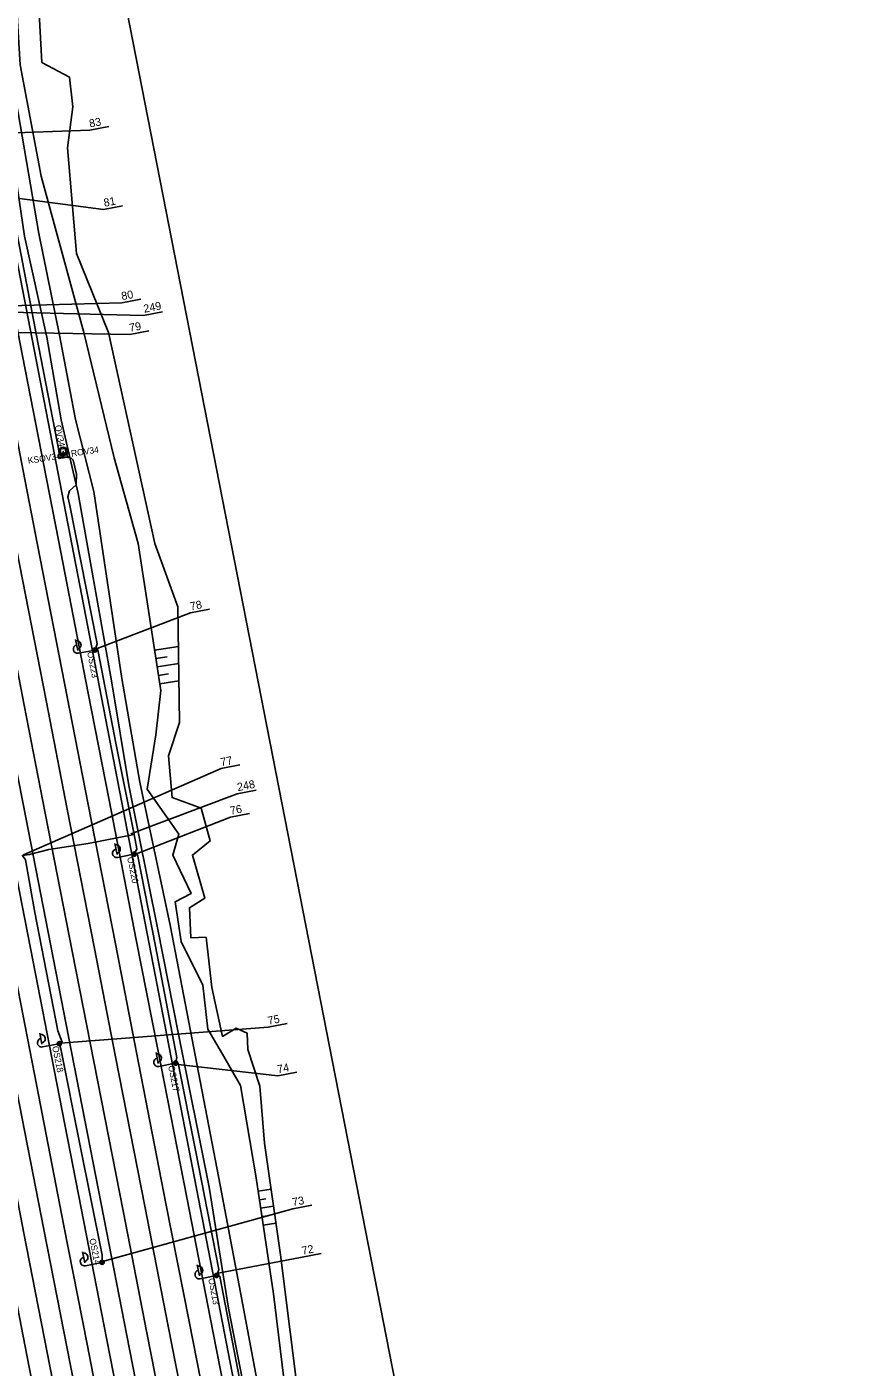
# Model space of a CAD drawing. Extents: x -545846 to -545044, y -1122650 to -1119108.
# Drawn here: x -545486.4 to -545292.2, y -1119892.9 to -1119578.9 of the extents above; entities that cross this region are included whole.
import ezdxf

# ---------------------------------------------------------------- set-up
doc = ezdxf.new("R2010")
doc.units = 0
for name, color, linetype in [('osvětlené plochy-hodnota-obrys', 7, 'Continuous'), ('so180602', 7, 'Continuous'), ('Vrstva 1', 7, 'Continuous'), ('Vrstva 10', 7, 'Continuous'), ('Vrstva 12', 7, 'Continuous'), ('Vrstva 12 - Trakce zaklady', 7, 'Continuous'), ('Vrstva 25', 7, 'Continuous'), ('Vrstva 26', 7, 'Continuous'), ('Vrstva 51', 7, 'Continuous'), ('Vrstva 62', 7, 'Continuous'), ('Vrstva 63', 7, 'Continuous')]:
    doc.layers.add(name, color=color, linetype=linetype)

msp = doc.modelspace()

# ---------------------------------------------------------------- linework, layer by layer
at = {"layer": 'osvětlené plochy-hodnota-obrys'}
msp.add_lwpolyline([(-545520.97, -1119506.47), (-545505.64, -1119546.72), (-545397.93, -1120102.85)], dxfattribs=at)
at = {"layer": 'Vrstva 1'}
for points in [[(-545506.26, -1119584.98), (-545505.64, -1119588.18), (-545501.7, -1119608.65), (-545497.83, -1119628.61), (-545492.89, -1119654.09), (-545487.27, -1119682.92), (-545483.88, -1119700.28)], [(-545501.4, -1119584.04), (-545500.78, -1119587.18), (-545496.82, -1119607.62), (-545492.98, -1119627.32), (-545488.03, -1119652.82), (-545482.44, -1119681.62), (-545479.01, -1119699.16)], [(-545504.04, -1119675.3), (-545496.76, -1119712.41), (-545491.63, -1119738.67), (-545486.65, -1119764.12), (-545480.23, -1119797.01), (-545475.32, -1119822.26), (-545468.39, -1119857.8), (-545462.99, -1119885.43), (-545456.77, -1119917.38), (-545451.56, -1119944.05), (-545446.59, -1119969.43), (-545441.08, -1119997.67), (-545435.96, -1120023.86), (-545430.59, -1120051.32), (-545426.85, -1120070.67)], [(-545512.75, -1119680.06), (-545506.04, -1119714.37), (-545500.99, -1119740.29), (-545495.97, -1119766.06), (-545489.56, -1119798.98), (-545484.63, -1119824.29), (-545477.72, -1119859.75), (-545472.31, -1119887.47), (-545466.08, -1119919.33), (-545460.87, -1119946.03), (-545455.91, -1119971.4), (-545450.38, -1119999.68), (-545445.29, -1120025.77), (-545439.89, -1120053.38), (-545436.18, -1120072.49)], [(-545508.3, -1119678.31), (-545501.41, -1119713.42), (-545496.34, -1119739.4), (-545491.32, -1119765.12), (-545484.91, -1119797.95), (-545479.98, -1119823.28), (-545473.04, -1119858.81), (-545467.63, -1119886.5), (-545461.42, -1119918.35), (-545456.18, -1119945.11), (-545451.23, -1119970.49), (-545445.73, -1119998.73), (-545440.63, -1120024.76), (-545435.23, -1120052.38), (-545431.51, -1120071.58)], [(-545526.85, -1119682.75), (-545520.07, -1119717.38), (-545515.03, -1119743.16), (-545509.97, -1119769.03), (-545503.62, -1119801.64), (-545498.65, -1119827.09), (-545491.8, -1119862.23), (-545486.29, -1119890.47), (-545480.04, -1119922.41), (-545474.85, -1119948.96), (-545469.96, -1119974), (-545464.39, -1120002.62), (-545459.33, -1120028.63), (-545453.88, -1120056.52), (-545450.25, -1120075.23)], [(-545522.17, -1119681.81), (-545515.38, -1119716.42), (-545510.35, -1119742.18), (-545505.33, -1119768), (-545498.9, -1119800.89), (-545493.99, -1119826.04), (-545487.08, -1119861.49), (-545481.61, -1119889.46), (-545475.38, -1119921.42), (-545470.2, -1119947.95), (-545465.28, -1119973.13), (-545459.72, -1120001.56), (-545454.6, -1120027.72), (-545449.19, -1120055.51), (-545445.53, -1120074.31)], [(-545517.39, -1119681.15), (-545510.7, -1119715.36), (-545505.65, -1119741.28), (-545500.67, -1119766.98), (-545494.24, -1119799.96), (-545489.36, -1119825.02), (-545482.41, -1119860.61), (-545476.97, -1119888.48), (-545470.74, -1119920.36), (-545465.53, -1119946.97), (-545460.61, -1119972.16), (-545455.05, -1120000.65), (-545449.96, -1120026.74), (-545444.56, -1120054.41), (-545440.88, -1120073.4)], [(-545479.01, -1119699.16), (-545472.02, -1119735), (-545467.16, -1119760.06), (-545460.78, -1119792.8), (-545455.81, -1119818.06), (-545448.88, -1119853.56), (-545443.47, -1119881.24), (-545437.18, -1119913.5), (-545431.96, -1119940.16), (-545427.07, -1119965.24), (-545421.65, -1119993.22), (-545416.45, -1120019.83), (-545411.17, -1120046.97), (-545407.29, -1120066.86)], [(-545488.74, -1119701.59), (-545481.88, -1119736.77), (-545476.93, -1119762.15), (-545470.57, -1119794.82), (-545465.63, -1119820.17), (-545458.72, -1119855.56), (-545453.29, -1119883.26), (-545447, -1119915.44), (-545441.82, -1119942.01), (-545436.87, -1119967.3), (-545431.4, -1119995.48), (-545426.21, -1120021.98), (-545420.91, -1120049.23), (-545417.12, -1120068.78)], [(-545483.88, -1119700.28), (-545476.97, -1119735.85), (-545472.05, -1119761.11), (-545465.67, -1119793.73), (-545460.72, -1119819.17), (-545453.82, -1119854.52), (-545448.39, -1119882.15), (-545442.08, -1119914.38), (-545436.89, -1119940.99), (-545431.97, -1119966.29), (-545426.49, -1119994.32), (-545421.32, -1120020.9), (-545416.02, -1120048.08), (-545412.17, -1120067.81)], [(-545493.36, -1119705.37), (-545486.99, -1119737.85), (-545482.07, -1119763.16), (-545475.68, -1119795.84), (-545470.7, -1119821.28), (-545463.79, -1119856.66), (-545458.35, -1119884.48), (-545452.09, -1119916.55), (-545446.9, -1119943.08), (-545441.96, -1119968.35), (-545436.44, -1119996.63), (-545431.34, -1120022.9), (-545425.98, -1120050.33), (-545422.21, -1120069.77)]]:
    msp.add_lwpolyline(points, dxfattribs=at)
at = {"layer": 'Vrstva 10'}
msp.add_line((-545554.37, -1119108.31), (-545292.19, -1120447.89), dxfattribs=at)
at = {"layer": 'Vrstva 12'}
msp.add_lwpolyline([(-545478.58, -1119677.89), (-545478.41, -1119679.07), (-545477.17, -1119678.94), (-545477.4, -1119677.71), (-545478.58, -1119677.89)], dxfattribs=at)
at = {"layer": 'Vrstva 12 - Trakce zaklady'}
msp.add_lwpolyline([(-545478.58, -1119677.89), (-545478.41, -1119679.07), (-545477.17, -1119678.94), (-545477.4, -1119677.71), (-545478.58, -1119677.89)], dxfattribs=at)
at = {"layer": 'Vrstva 25'}
for p, q in [((-545474.47, -1119724.99), (-545474.98, -1119722.44)), ((-545470.9, -1119725), (-545474.34, -1119725.68)), ((-545470.18, -1119725.35), (-545470.91, -1119724.86)), ((-545469.94, -1119725.05), (-545470.73, -1119724.52)), ((-545465.27, -1119772.8), (-545465.78, -1119770.26)), ((-545461.7, -1119772.8), (-545465.13, -1119773.49)), ((-545460.97, -1119773.14), (-545461.7, -1119772.66)), ((-545460.73, -1119772.85), (-545461.53, -1119772.32)), ((-545482.85, -1119817.21), (-545483.36, -1119814.66)), ((-545479.28, -1119817.21), (-545482.72, -1119817.89)), ((-545478.56, -1119817.56), (-545479.29, -1119817.07)), ((-545478.32, -1119817.27), (-545479.11, -1119816.73)), ((-545455.63, -1119821.75), (-545456.14, -1119819.2)), ((-545452.06, -1119821.75), (-545455.5, -1119822.44)), ((-545451.34, -1119822.09), (-545452.07, -1119821.61)), ((-545451.1, -1119821.8), (-545451.89, -1119821.27)), ((-545472.83, -1119868.43), (-545473.34, -1119865.89)), ((-545469.26, -1119868.43), (-545472.7, -1119869.12)), ((-545468.54, -1119868.77), (-545469.27, -1119868.29)), ((-545468.3, -1119868.48), (-545469.09, -1119867.95)), ((-545445.98, -1119871.48), (-545446.48, -1119868.93)), ((-545442.41, -1119871.5), (-545445.84, -1119872.17)), ((-545441.68, -1119871.84), (-545442.41, -1119871.35)), ((-545441.44, -1119871.55), (-545442.24, -1119871.02))]:
    msp.add_line(p, q, dxfattribs=at)
for points in [[(-545477.03, -1119678.78), (-545476.89, -1119679.77), (-545478.87, -1119680.06), (-545479.01, -1119679.07), (-545477.03, -1119678.78)], [(-545476.55, -1119678.57), (-545476.41, -1119679.56), (-545478.39, -1119679.85), (-545478.53, -1119678.86), (-545476.55, -1119678.57)]]:
    msp.add_lwpolyline(points, dxfattribs=at)
for centre, radius in [((-545477.87, -1119678.39), 1), ((-545470.41, -1119724.91), 0.5), ((-545470.41, -1119724.91), 0.5), ((-545461.21, -1119772.7), 0.5), ((-545461.21, -1119772.7), 0.5), ((-545478.79, -1119817.12), 0.5), ((-545478.79, -1119817.12), 0.5), ((-545451.57, -1119821.65), 0.5), ((-545451.57, -1119821.65), 0.5), ((-545468.77, -1119868.33), 0.5), ((-545468.77, -1119868.33), 0.5), ((-545441.92, -1119871.4), 0.5), ((-545441.92, -1119871.4), 0.5)]:
    msp.add_circle(centre, radius, dxfattribs=at)
for centre, start, end in [((-545474.53, -1119724.7), 101.1718, 281.1718), ((-545474.71, -1119723.72), 280.4692, 101.8744), ((-545465.33, -1119772.51), 101.3492, 281.3492), ((-545465.51, -1119771.53), 280.6467, 102.0518), ((-545483.09, -1119815.93), 280.5247, 101.9298), ((-545482.91, -1119816.91), 101.2273, 281.2273), ((-545455.69, -1119821.46), 101.3274, 281.3274), ((-545455.88, -1119820.48), 280.6249, 102.03), ((-545472.89, -1119868.14), 101.3328, 281.3328), ((-545473.08, -1119867.16), 280.6302, 102.0353), ((-545446.04, -1119871.18), 101.0333, 281.0333), ((-545446.21, -1119870.2), 280.3307, 101.7359)]:
    msp.add_arc(centre, 1, start, end, dxfattribs=at)
at = {"layer": 'Vrstva 26'}
for points in [[(-545490.42, -1119618.51), (-545484.14, -1119651.23), (-545478.73, -1119678.93), (-545477.77, -1119679.65)], [(-545477.87, -1119678.39), (-545477.87, -1119678.39), (-545477.86, -1119678.62), (-545477.77, -1119679.01), (-545477.47, -1119679.21), (-545477.95, -1119679.42), (-545477.77, -1119679.65)], [(-545477.77, -1119679.65), (-545475.99, -1119679.96), (-545475.55, -1119680.44), (-545474.78, -1119683.72), (-545474.82, -1119686.21), (-545476.39, -1119687.61), (-545476.83, -1119689.04), (-545476.34, -1119691.05), (-545469.94, -1119723.46), (-545470.41, -1119724.91), (-545469.75, -1119724.85), (-545465.52, -1119747.09), (-545461.3, -1119768.11), (-545460.63, -1119771.47), (-545461.21, -1119772.7), (-545460.51, -1119772.81), (-545456.27, -1119794.26), (-545451.25, -1119820.33), (-545451.57, -1119821.65), (-545450.97, -1119821.66), (-545446.81, -1119842.43), (-545441.43, -1119870.01), (-545441.92, -1119871.4), (-545441.17, -1119871.61), (-545436.23, -1119897.54)], [(-545468.77, -1119868.33), (-545468.76, -1119866.68), (-545473.98, -1119840.62), (-545478.41, -1119818.36), (-545478.79, -1119817.12), (-545478.11, -1119816.77), (-545479.15, -1119814.09), (-545484.55, -1119786.38), (-545486.75, -1119774.08), (-545487.42, -1119773.02), (-545485.8, -1119772.82), (-545481.22, -1119771.65), (-545472.05, -1119770.2), (-545461.3, -1119768.11)], [(-545485.8, -1119772.82), (-545481.22, -1119771.65), (-545472.05, -1119770.2), (-545461.3, -1119768.11)]]:
    msp.add_lwpolyline(points, dxfattribs=at)
at = {"layer": 'Vrstva 51'}
for points in [[(-545511.73, -1119517.03), (-545497, -1119556.5), (-545492.54, -1119576.26), (-545488.43, -1119599.11), (-545483.62, -1119627.38), (-545478.79, -1119651.18), (-545474.99, -1119670.94), (-545470.7, -1119687.75)], [(-545514.46, -1119518.32), (-545500.04, -1119556.88), (-545495.23, -1119576.45), (-545491.1, -1119599.78), (-545486.96, -1119627.99), (-545481.75, -1119651.67), (-545478.35, -1119671.03), (-545474.36, -1119688.26)], [(-545474.36, -1119688.26), (-545466.58, -1119732.11), (-545462.51, -1119756.66), (-545455.83, -1119789.99), (-545450.92, -1119814.9), (-545443.72, -1119850.69), (-545439.16, -1119879.07), (-545432.58, -1119913.19), (-545426.88, -1119936.67), (-545422.74, -1119962.51), (-545418.33, -1119990.02), (-545411.43, -1120016.49), (-545406.24, -1120044.57), (-545403.53, -1120065.52), (-545401.18, -1120088.87), (-545397.02, -1120115.44), (-545395.2, -1120135.68), (-545394.06, -1120143.26), (-545386.49, -1120187.75)], [(-545470.7, -1119687.75), (-545464.14, -1119731.58), (-545459.97, -1119755.88), (-545452.87, -1119789.33), (-545448.1, -1119814.11), (-545441.14, -1119850.22), (-545435.79, -1119878.29), (-545429.37, -1119912.85), (-545423.03, -1119935.8), (-545419.14, -1119961.66), (-545414.86, -1119988.76), (-545403.01, -1120044.19), (-545400.26, -1120064.29), (-545395.92, -1120087.78), (-545392.45, -1120114.4), (-545391.18, -1120135.43), (-545389.94, -1120142.63), (-545383.23, -1120188.01)]]:
    msp.add_lwpolyline(points, dxfattribs=at)
at = {"layer": 'Vrstva 62'}
for points in [[(-545497.33, -1119511.25), (-545486.34, -1119534.72), (-545495.96, -1119540.92), (-545493.16, -1119551.22), (-545484.39, -1119549.67), (-545482.18, -1119562.89), (-545489.11, -1119568.39), (-545487.95, -1119587.82), (-545483.04, -1119613.89), (-545473.08, -1119650.55), (-545465.95, -1119679.91), (-545460.34, -1119700)], [(-545456.42, -1119700), (-545467.27, -1119650.55), (-545474.74, -1119632.03), (-545476.88, -1119607.3), (-545475.61, -1119597.69), (-545476.4, -1119590.7), (-545482.87, -1119587.28), (-545483.91, -1119568.42), (-545477.93, -1119559.36), (-545477.27, -1119553.64), (-545481.58, -1119546.45), (-545474.62, -1119544.67), (-545475.41, -1119539.39), (-545487.42, -1119541.16), (-545482.06, -1119536.75), (-545482.51, -1119529.89), (-545491.65, -1119512.29)], [(-545460.34, -1119700), (-545455.04, -1119734.4), (-545456.21, -1119744.77), (-545458.22, -1119757.52), (-545450.81, -1119768.02), (-545452.25, -1119772.98), (-545447.95, -1119781.96), (-545451.66, -1119783.89), (-545450.23, -1119793.15), (-545445.19, -1119803.39), (-545443.99, -1119813.68), (-545440.57, -1119819.58), (-545436.33, -1119826.92), (-545432.71, -1119848.57), (-545428.67, -1119875.73), (-545425.81, -1119898.75), (-545427.91, -1119901.48), (-545426.27, -1119914.53), (-545423.22, -1119917.43), (-545417.81, -1119919.21), (-545395.4, -1119920.64), (-545395.38, -1119920.67)], [(-545422.45, -1119902.61), (-545427.03, -1119866.59), (-545430.71, -1119840.42), (-545431.87, -1119827.07), (-545434.68, -1119818.51), (-545434.81, -1119814.65), (-545437.36, -1119813.49), (-545440.62, -1119815.4), (-545443.07, -1119803.98), (-545444.41, -1119792.18), (-545448, -1119792.29), (-545448.34, -1119785.29), (-545444.7, -1119783.01), (-545447.64, -1119772.93), (-545443.45, -1119769.61), (-545445.57, -1119761.98), (-545452.38, -1119759.47), (-545453.25, -1119749.7), (-545450.63, -1119741.88), (-545451.04, -1119714.8), (-545456.42, -1119700)], [(-545456.5, -1119724.92), (-545450.9, -1119724.05)], [(-545456.19, -1119726.89), (-545453.53, -1119726.48)], [(-545455.89, -1119728.87), (-545450.84, -1119728.09)], [(-545455.58, -1119730.85), (-545453.2, -1119730.48)], [(-545455.28, -1119732.82), (-545450.78, -1119732.13)], [(-545432.25, -1119851.69), (-545429.19, -1119851.23)], [(-545431.95, -1119853.66), (-545430.43, -1119853.44)], [(-545431.66, -1119855.64), (-545428.63, -1119855.19)], [(-545431.36, -1119857.62), (-545429.86, -1119857.4)], [(-545431.07, -1119859.6), (-545428.08, -1119859.15)]]:
    msp.add_lwpolyline(points, dxfattribs=at)
at = {"layer": 'Vrstva 63'}
for p, q in [((-545471.67, -1119603.12), (-545519.87, -1119604.96)), ((-545467.22, -1119602.26), (-545471.67, -1119603.12)), ((-545468.42, -1119621.71), (-545491.06, -1119618.73)), ((-545463.97, -1119620.84), (-545468.42, -1119621.71)), ((-545459.69, -1119642.7), (-545464.14, -1119643.56)), ((-545464.14, -1119643.56), (-545571.89, -1119646.62)), ((-545459.08, -1119646.57), (-545512.02, -1119645.22)), ((-545454.64, -1119645.7), (-545459.08, -1119646.57)), ((-545454.64, -1119645.7), (-545459.08, -1119646.57)), ((-545454.64, -1119645.7), (-545459.08, -1119646.57)), ((-545462.3, -1119650.98), (-545535.41, -1119649.74)), ((-545457.86, -1119650.12), (-545462.3, -1119650.98)), ((-545448.07, -1119716.21), (-545470.36, -1119724.7)), ((-545443.63, -1119715.35), (-545448.07, -1119716.21)), ((-545440.93, -1119752.7), (-545487.17, -1119772.85)), ((-545436.49, -1119751.84), (-545440.93, -1119752.7)), ((-545437.15, -1119758.61), (-545462.07, -1119767.98)), ((-545432.71, -1119757.74), (-545437.15, -1119758.61)), ((-545432.71, -1119757.74), (-545437.15, -1119758.61)), ((-545432.71, -1119757.74), (-545437.15, -1119758.61)), ((-545438.7, -1119764.07), (-545461.14, -1119772.83)), ((-545434.26, -1119763.21), (-545438.7, -1119764.07)), ((-545429.86, -1119813.27), (-545478.55, -1119817.02)), ((-545425.42, -1119812.41), (-545429.86, -1119813.27)), ((-545427.64, -1119824.64), (-545451.69, -1119821.93)), ((-545423.19, -1119823.78), (-545427.64, -1119824.64)), ((-545424.13, -1119855.77), (-545468.71, -1119868.1)), ((-545419.69, -1119854.91), (-545424.13, -1119855.77)), ((-545421.91, -1119867.14), (-545442.02, -1119870.98)), ((-545417.46, -1119866.28), (-545421.91, -1119867.14))]:
    msp.add_line(p, q, dxfattribs=at)

# ---------------------------------------------------------------- texts
at = {"layer": 'so180602'}
for s, p in [('83', (-545471.61, -1119602.54)), ('81', (-545468.22, -1119621.1)), ('80', (-545464.08, -1119642.98)), ('249', (-545458.89, -1119645.93)), ('79', (-545462.24, -1119650.4)), ('78', (-545448.01, -1119715.63)), ('77', (-545440.86, -1119752.12)), ('248', (-545436.96, -1119757.97)), ('76', (-545438.64, -1119763.49)), ('75', (-545429.8, -1119812.69)), ('74', (-545427.58, -1119824.06)), ('73', (-545424.07, -1119855.19)), ('72', (-545421.83, -1119866.56))]:
    msp.add_text(s, height=1.875, rotation=10.9955, dxfattribs=at).set_placement(p)
at = {"layer": 'Vrstva 25'}
for s, rotation, p in [('OV34', 281.0364, (-545479.88, -1119672.37)), ('ROV34', 8.4621, (-545475.95, -1119679.64)), ('KSOV34', 8.4621, (-545486.06, -1119681.31)), ('OS223', 280.7735, (-545472.29, -1119725.41)), ('OS220', 281.1804, (-545462.91, -1119773.52)), ('OS218', 281.2273, (-545480.48, -1119817.83)), ('OS217', 281.3274, (-545453.32, -1119822.36)), ('OS214', 281.3328, (-545471.78, -1119862.88)), ('OS213', 280.7886, (-545443.93, -1119872.19))]:
    msp.add_text(s, height=1.5, rotation=rotation, dxfattribs=at).set_placement(p)

doc.saveas('drawing.dxf')
